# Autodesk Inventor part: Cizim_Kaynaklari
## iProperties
Company: Autodesk, Inc.
Shininess: 64.0
Length Units: 11269
Angle Units: 11279
Time Units: 11290
Mass Units: 11283
Length Display Precision: 3
Angle Display Precision: 2
Compacted: True
Part Number: Cizim_Kaynaklari
Document SubType Name: Modeling
Created: 2003-11
Catalog Web Link: www.autodesk.com
Vendor: Autodesk, Inc.
Designer: Administrator
Manufacturer: Standard
Standards Organization: Custom
Density: 1 g/cm^3
Density: 0.0
Volumn: 0.0
Area: 0.0
PropertySet Name: Model Information
Control State: 0
Master: False
Checked Out: False
Author: Administrator
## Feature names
1. Extrusion1
2. Extrusion2
3. Hole1
4. Extrusion3
5. Hole2
6. Hole3
7. Hole4
8. Hole5
9. Extrusion4
10. Chamfer1
